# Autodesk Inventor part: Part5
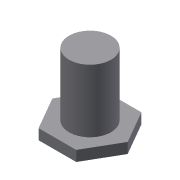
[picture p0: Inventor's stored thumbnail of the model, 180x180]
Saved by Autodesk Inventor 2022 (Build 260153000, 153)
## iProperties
Created: 2008-05
Part Number: Part5
Document SubType Name: Modeling
Designer: CADCIM
Density: 1 g/cm^3
Material: Generic
Appearance: Default
Author: CADCIM
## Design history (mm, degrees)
sketch "Sketch1"
  geometry: C1 r 2 at (-7.12, 11.618)
  constraints: 1 centre point
  dimensions: "d2" = 4 diameter of C1
extrude "Extrusion1" new body sketch "Sketch1" distance "d0" = 6; taper "d1" = 0 deg
sketch "Sketch2"
  geometry: L1 (-3.598, 0)-(-1.799, 3.116); L2 (-1.799, 3.116)-(1.799, 3.116); L3 (1.799, 3.116)-(3.598, 0); L4 (3.598, 0)-(1.799, -3.116); L5 (1.799, -3.116)-(-1.799, -3.116); L6 (-1.799, -3.116)-(-3.598, 0); C1 r 2 at (0, 0) reference; 1 further point
  constraints: 12 end point, 1 coincident, 13 other
extrude "Extrusion2" join sketch "Sketch2" distance "d3" = 1; taper "d4" = 0 deg
body "Solid1"
